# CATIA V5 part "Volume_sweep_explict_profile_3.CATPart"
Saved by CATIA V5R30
Part number: Part1
Bounding box of the stored display mesh (mm): x -10 to 10, y -11.899 to 23.172, z 0 to 127.486
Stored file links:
  D:\PROJECTS\CATIA V56R 2020\Resources\Parts File\c17_catia_v6_6r2020_prt\Volume_sweep_explict_profile_3.CATPart
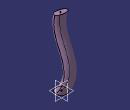
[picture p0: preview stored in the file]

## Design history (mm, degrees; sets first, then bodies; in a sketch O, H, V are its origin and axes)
Set1
  Sketch1 on xy-plane, origin (0, 0, 0), H (1, 0, 0), V (0, 1, 0)
    circle A1 centre (0, 0) radius 10
    radius A1 = 10
  Sketch2 on yz-plane, origin (0, 0, 0), H (0, 1, 0), V (0, 0, 1)
    spline S1 through (0, 0) (11.9407, 56.843) (-3.4307, 102.6672) (-1.4005, 123.8391)
    point P1 (0, 0)
    coincidence: P1 O
  Sweep1: type Unspec, Profile Sketch1, Guide Sketch2, AngleRef 0, PullingDir zx-plane
Body1 (main body)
